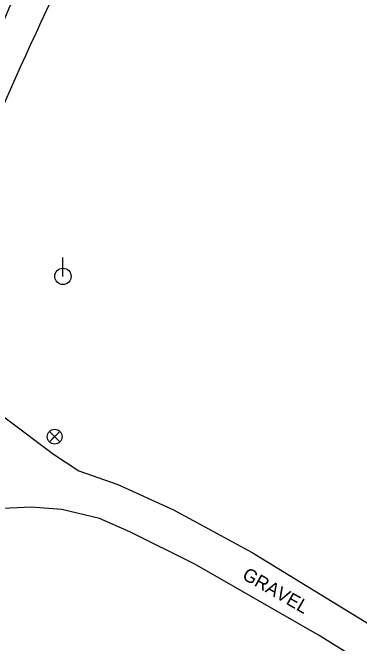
# Model space of a CAD drawing. Extents: x 1435573 to 1437263, y 981340 to 982884.
# Drawn here: x 1435933.9 to 1436038, y 981720.6 to 981909.7 of the extents above; entities that cross this region are included whole.
import ezdxf

# ---------------------------------------------------------------- set-up
doc = ezdxf.new("R2010")
doc.units = 0
for name, color, linetype in [('Exist Horizontal Alignment', 7, 'Continuous'), ('Exist Right of Way Line', 7, 'Continuous'), ('Exist Roads EOP', 7, 'Continuous'), ('Exist Roads Soil', 7, 'Continuous'), ('Exist Roads Soil Text', 7, 'Continuous'), ('Exist Utilities Power Pole CELL', 7, 'Continuous'), ('Exist Utilities Water Valve CELL', 7, 'Continuous')]:
    doc.layers.add(name, color=color, linetype=linetype)

# ---------------------------------------------------------------- blocks, each defined once
blk = doc.blocks.new('EXIST UTILITIES WATER VALVE')
at = {"layer": 'Exist Utilities Water Valve CELL'}
blk.add_lwpolyline([(0.0315, 0.0315), (-0.0315, -0.0315), (0, 0), (0.0315, -0.0315), (-0.0315, 0.0315)], dxfattribs=at)
blk.add_circle((0, 0), 0.0445, dxfattribs=at)
blk = doc.blocks.new('EXIST UTILITIES POWER POLE')
at = {"layer": 'Exist Utilities Power Pole CELL'}
for q in [(0, 0.1125), (0, 0)]:
    blk.add_line((0, 0), q, dxfattribs=at)
blk.add_circle((0, 0), 0.049, dxfattribs=at)

msp = doc.modelspace()

# ---------------------------------------------------------------- linework, layer by layer
at = {"layer": 'Exist Horizontal Alignment'}
msp.add_arc((1437742.01, 981076.34), 2000, 149.52518, 156.40919, dxfattribs=at)
at = {"layer": 'Exist Right of Way Line'}
for radius in [2018, 1982]:
    msp.add_arc((1437742.01, 981076.34), radius, 149.52518, 156.40919, dxfattribs=at)
at = {"layer": 'Exist Roads EOP'}
for points in [[(1436168.25, 982354.25), (1436159.59, 982341.51), (1436138.87, 982307.92), (1436116.45, 982270.71), (1436094.59, 982234.3), (1436072.39, 982197.46), (1436049.68, 982158.52), (1436026.6, 982119.74), (1436003.23, 982078.86), (1435983.99, 982044.69), (1435963.78, 982007.01), (1435943.65, 981966.84), (1435922.15, 981922.09), (1435903.52, 981881.23), (1435884.45, 981840.59), (1435866.4, 981798.52)], [(1436177.12, 982349.86), (1436168.84, 982336.18), (1436150.23, 982301.68), (1436128.75, 982263.64), (1436107.21, 982226.88), (1436085.56, 982190.23), (1436062.44, 982151.3), (1436039.53, 982112.34), (1436015.81, 982071.47), (1435996.75, 982037.94), (1435976.48, 982000.31), (1435956.5, 981960.4), (1435935.19, 981915.99), (1435916.41, 981875.42), (1435898.23, 981835.84), (1435879.29, 981793.08)]]:
    msp.add_spline(points, degree=3, dxfattribs=at)
at = {"layer": 'Exist Roads Soil'}
for points in [[(1435890.27, 981816.14), (1435893.58, 981812.84), (1435898.16, 981809.78), (1435909.93, 981802.79), (1435932.12, 981787.93), (1435946.22, 981777.28), (1435953.79, 981772.35), (1435965.45, 981768.23), (1435982.16, 981760.57), (1436005.84, 981747.77), (1436045.77, 981723.3), (1436083.36, 981699.08), (1436109.24, 981682.98)], [(1436104.74, 981675.21), (1436065.5, 981698.26), (1436025.93, 981722.9), (1435988.61, 981744.29), (1435969.14, 981754.03), (1435959.99, 981758.06), (1435948.68, 981760.7), (1435939.51, 981761.38), (1435928.82, 981760.95), (1435911.51, 981758.41), (1435879.99, 981751.78), (1435869.39, 981748.9), (1435860.25, 981742.74)]]:
    msp.add_lwpolyline(points, dxfattribs=at)

# ---------------------------------------------------------------- block references
at = {"layer": 'Exist Utilities Power Pole CELL', "xscale": 50, "yscale": 50}
msp.add_blockref('EXIST UTILITIES POWER POLE', (1435949.01, 981830.62), dxfattribs=at)
at = {"layer": 'Exist Utilities Water Valve CELL', "xscale": 50, "yscale": 50}
msp.add_blockref('EXIST UTILITIES WATER VALVE', (1435946.53, 981782.57), dxfattribs=at)

# ---------------------------------------------------------------- texts
at = {"layer": 'Exist Roads Soil Text'}
msp.add_text('GRAVEL', height=4, rotation=330.1875, dxfattribs=at).set_placement((1436002.52, 981740.08))

doc.saveas('drawing.dxf')
